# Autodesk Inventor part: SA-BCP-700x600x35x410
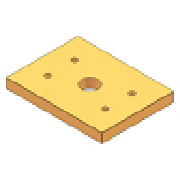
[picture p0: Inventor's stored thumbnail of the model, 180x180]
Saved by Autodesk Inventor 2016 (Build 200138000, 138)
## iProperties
Created: 2015-02
Part Number: SA-BCP-700x600x35x410
Material: S 55 C
Description: Bottom Clamping Plate
Document SubType Name: Modeling
Designer: Sandeep
Standard Revision: 1
Manufacturer: FUTABA
Language: en-US
Size Designation: 700x600x35x410
Categories: <MemberInstance><Categories><Category DisplayName="Mold" InternalName="349578f2-f4d4-4954-8c09-8e99297a61c0" Mnemonic="MOLD"><Category DisplayName="Mold Plates"
Density: 7.85 g/cm^3
Appearance: Orange (Pale)
IsCustomPart: 1
Author: Sandeep
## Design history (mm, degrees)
sketch "Sketch1"
  geometry: L1 (-300, 350)-(300, 350); L2 (300, 350)-(300, -350); L3 (300, -350)-(-300, -350); L4 (-300, -350)-(-300, 350); C1 r 17.5 at (0, 0); 4 further points
  constraints: 8 end point, 2 midpoint, 2 parallel, 1 centre point, 1 coincident, 1 horizontal, 1 horizontal alignment, 1 perpendicular, 1 vertical alignment
  dimensions: "d72" = 600 distance between parallel lines of L2 L4 (= W_); "d73" = 700 distance between parallel lines of L3 L1 (= L); "d74" = 35 diameter of C1 (= dB); "d75" = 205 horizontal distance of point (0, 0) point (-205, 243) (= 0.5 x S1_W); "d76" = 243 vertical distance of point (0, 0) point (-205, 243) (= 0.5 x S1_L)
body "Solid1"
extrude "Extrusion1" new body sketch "Sketch1" distance "d77" = 35 (= H_); taper "d78" = 0 deg
hole "Hole1" sketch "Sketch1" diameter "d79" = 18 (= S1_d1); stored, may be unused: countersink angle "d83" = 90 deg, drill point angle "d85" = 0 deg; dims "d80" = 6, "d81" = 26 (= S1_d2), "d82" = 17.5 (= S1_k), "d84" = 35 (= H_)
pattern_linear "Rectangular Pattern1" dims "d88" = 243 (computed from S1_L, Ns)
extrude "Extrusion2" cut sketch "Sketch1" distance "d92" = 35 (= H_); taper "d93" = 0 deg
chamfer "Chamfer1" distance "d94" = 0.5; stored, may be unused: second distance "d95" = 2, angle "d96" = 45 deg
other parameters: "L" = 700 [user parameter; used in 1 equation term], "W_" = 600 [user parameter; used in 1 equation term], "H_" = 35 [user parameter; used in 3 equation terms], "S1_d1" = 18 [user parameter; used in 1 equation term], "S1_d2" = 26 [user parameter; used in 1 equation term], "S1_k" = 17.5 [user parameter; used in 1 equation term], "S1_L" = 486 [user parameter; used in 2 equation terms], "dB" = 35 [user parameter; used in 1 equation term]
